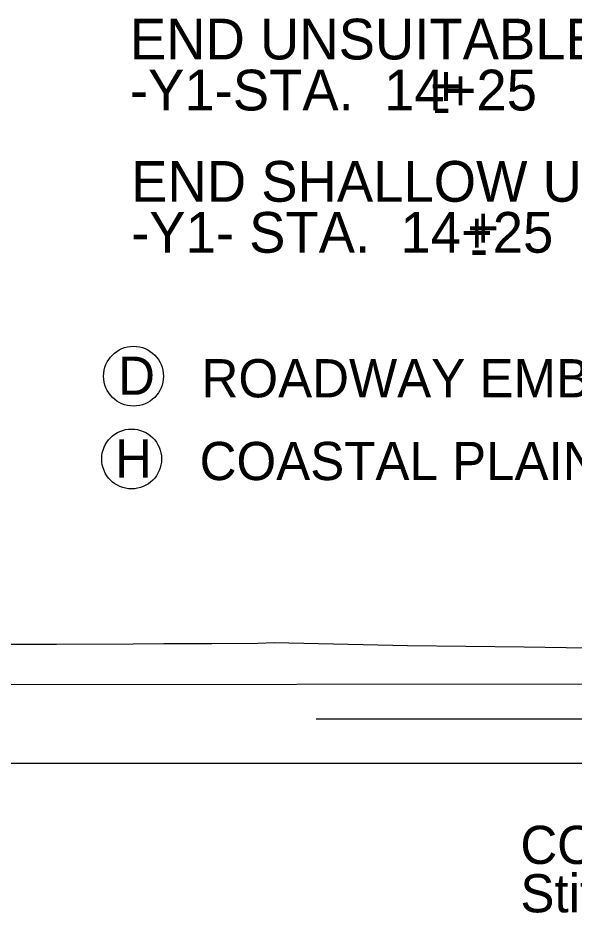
# Model space of a CAD drawing. Extents: x -516 to 303, y -10 to 5017.
# Drawn here: x 103.36 to 125.24, y 3993.69 to 4029.26 of the extents above; entities that cross this region are included whole.
import ezdxf

# ---------------------------------------------------------------- set-up
doc = ezdxf.new("R2010")
doc.units = 0
for name, color, linetype in [('Exist Cross Section Cell', 7, 'Continuous'), ('Exist XS Ground Line', 7, 'Continuous'), ('Prop Road Sect_ Material - Bubble + Leader + Bubble Tx', 7, 'Continuous'), ('Prop Road Sect_ Material - Contact (General - Major)', 7, 'Continuous'), ('Prop Road Sect_ Material - Contact (General - Minor)', 7, 'Continuous'), ('Prop Road Sect_ Material - Tx (Composite Desc)', 7, 'Continuous'), ('Prop Road Sect_ Recs - UC Shallow (Tx)', 7, 'Continuous'), ('Prop Road Sect_ Recs - UUC (Tx)', 7, 'Continuous')]:
    doc.layers.add(name, color=color, linetype=linetype)

msp = doc.modelspace()

# ---------------------------------------------------------------- linework, layer by layer
at = {"layer": 'Exist Cross Section Cell'}
msp.add_line((0, 4000), (150, 4000), dxfattribs=at)
at = {"layer": 'Exist XS Ground Line'}
msp.add_lwpolyline([(101.707, 4004.669), (104.871, 4004.674), (107.888, 4004.685), (109.088, 4004.693), (110.974, 4004.699), (112.777, 4004.709), (113.424, 4004.739), (118.661, 4004.616), (123.254, 4004.569), (133.137, 4004.41)], dxfattribs=at)
at = {"layer": 'Prop Road Sect_ Material - Bubble + Leader + Bubble Tx'}
for centre in [(107.896, 4015.197), (107.821, 4011.947)]:
    msp.add_circle(centre, 1.176, dxfattribs=at)
at = {"layer": 'Prop Road Sect_ Material - Contact (General - Major)'}
msp.add_line((162.764, 4003.154), (77.352, 4003.036), dxfattribs=at)
at = {"layer": 'Prop Road Sect_ Material - Contact (General - Minor)'}
msp.add_line((115.068, 4001.737), (187.085, 4001.737), dxfattribs=at)

# ---------------------------------------------------------------- texts
at = {"layer": 'Prop Road Sect_ Material - Tx (Composite Desc)'}
for s, p in [('D', (107.291, 4014.466)), ('ROADWAY EMBANKMENT: Brown, Medium Stiff to Stiff, Silty CLAY (A-7-6), Highly Plastic, Moist', (110.569, 4014.367)), ('H', (107.169, 4011.216)), ('COASTAL PLAIN: Black to Gray, Stiff, Sandy SILT (A-4), Moist (Black Creek Formation)', (110.494, 4011.117)), ('COASTAL PLAIN: Orange-Brown and Gray, Soft to Medium ', (123.1, 3996.04)), ('Stiff, Sandy CLAY (A-6), Moist to Wet (Black Creek Formation)', (123.1, 3994.139))]:
    msp.add_text(s, height=1.5, dxfattribs=at).set_placement(p)
at = {"layer": 'Prop Road Sect_ Recs - UC Shallow (Tx)'}
for s, p in [('END SHALLOW UNDERCUT FOR AGGREGATE SUBGRADE', (107.803, 4022.05)), ('-Y1- STA.  14+25', (107.803, 4020.047)), ('+', (121.012, 4020.233)), ('-', (121.12, 4019.428))]:
    msp.add_text(s, height=1.6, dxfattribs=at).set_placement(p)
at = {"layer": 'Prop Road Sect_ Recs - UUC (Tx)'}
for s, p in [('END UNSUITABLE UNCLASSIFIED EXCAVATION-MATERIAL TO BE WASTED', (107.755, 4027.638)), ('-Y1-STA.  14+25', (107.755, 4025.635)), ('+', (119.548, 4025.808)), ('-', (119.655, 4025.003))]:
    msp.add_text(s, height=1.6, dxfattribs=at).set_placement(p)

doc.saveas('drawing.dxf')
